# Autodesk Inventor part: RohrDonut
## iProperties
Created: 2011-02
Part Number: RohrDonut
Document SubType Name: Modeling
Designer: student
Author: student
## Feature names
1. Extrusion1
2. Extrusion2
3. Rundung1 [Fillet]
